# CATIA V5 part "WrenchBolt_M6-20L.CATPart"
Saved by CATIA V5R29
Part number: WrenchBolt_M6-20L
Source: Unknown
Bounding box of the stored display mesh (mm): x -5.11 to 5.11, y -5.11 to 5.11, z -20 to 6
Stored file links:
  C:\가치같이\SmartFactory_BoxErectorConveyor\Boxing(under)\WrenchBolt_M6-20L.CATPart
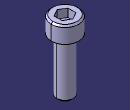
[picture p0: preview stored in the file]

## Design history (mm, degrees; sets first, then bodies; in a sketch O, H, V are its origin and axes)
Body1 (main body)
  Solid1 "PartBody": solid without history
